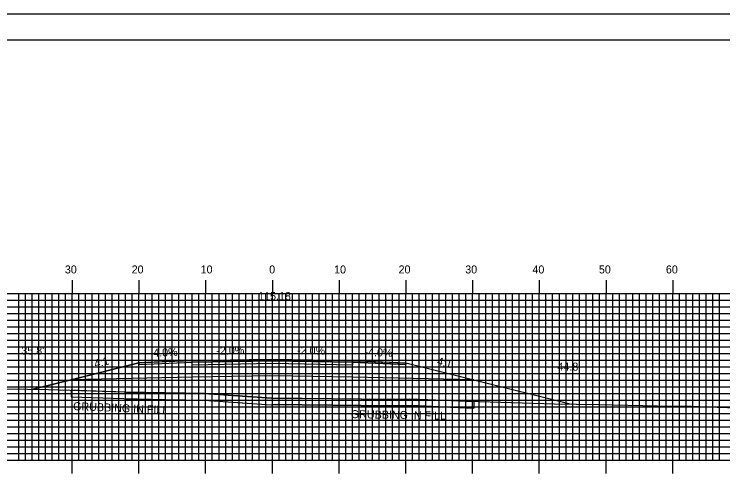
# Model space of a CAD drawing. Extents: x 1772809 to 1773153, y 442591 to 442811.
# Drawn here: x 1772936.4 to 1773042.6, y 442741.2 to 442810.5 of the extents above; entities that cross this region are included whole.
import ezdxf

# ---------------------------------------------------------------- set-up
doc = ezdxf.new("R2010")
doc.units = 0
for name, color, linetype in [('ANNOTATION', 7, 'Continuous'), ('BORDER', 7, 'Continuous'), ('D_Roadway_Centerline', 7, 'Continuous'), ('D_Roadway_Centerline_Text', 7, 'Continuous'), ('D_Roadway_Edge_Shoulder', 7, 'Continuous'), ('D_Roadway_Edge_TW', 7, 'Continuous'), ('D_Roadway_Pavement', 7, 'Continuous'), ('D_Roadway_SlopeLines', 7, 'Continuous'), ('D_Roadway_SubGrade', 7, 'Continuous'), ('D_Text_Standard', 7, 'Continuous'), ('GRUBBING IN FILL', 7, 'Continuous'), ('H_V ANNOTATION', 7, 'Continuous'), ('MAJOR', 7, 'Continuous'), ('MINOR', 7, 'Continuous'), ('PLOT BOUNDARY', 7, 'Continuous'), ('S_Roadway_Centerline', 7, 'Continuous')]:
    doc.layers.add(name, color=color, linetype=linetype)

msp = doc.modelspace()

# ---------------------------------------------------------------- linework, layer by layer
at = {"layer": 'BORDER'}
msp.add_lwpolyline([(1772825.52, 442596.67), (1773145.52, 442596.67), (1773145.52, 442806.67), (1772825.52, 442806.67)], close=True, dxfattribs=at)
at = {"layer": 'D_Roadway_Centerline'}
msp.add_lwpolyline([(1772939.27, 442754.32), (1772943.12, 442755.28), (1772944.95, 442755.74), (1772955.12, 442758.28), (1772957.96, 442758.4), (1772963.12, 442758.6), (1772963.12, 442758.6), (1772971.65, 442758.77), (1772975.12, 442758.84), (1772987.12, 442758.6), (1772987.12, 442758.6), (1772991.4, 442758.43), (1772995.12, 442758.28), (1772999.33, 442757.23), (1773005.29, 442755.74), (1773005.3, 442755.74), (1773019.94, 442752.08)], dxfattribs=at)
at = {"layer": 'D_Roadway_Edge_Shoulder'}
for points in [[(1772963.12, 442758.6), (1772955.12, 442758.28), (1772955.12, 442758.03), (1772963.12, 442758.35)], [(1772987.12, 442758.6), (1772995.12, 442758.28), (1772995.12, 442758.03), (1772987.12, 442758.35)]]:
    msp.add_lwpolyline(points, close=True, dxfattribs=at)
at = {"layer": 'D_Roadway_Edge_TW'}
msp.add_lwpolyline([(1772963.12, 442758.35), (1772963.12, 442758.6), (1772975.12, 442758.84), (1772987.12, 442758.6), (1772987.12, 442758.35), (1772975.12, 442758.59)], close=True, dxfattribs=at)
at = {"layer": 'D_Roadway_Pavement'}
msp.add_lwpolyline([(1772963.12, 442757.94), (1772963.12, 442758.35), (1772975.12, 442758.59), (1772987.12, 442758.35), (1772987.12, 442757.94), (1772975.12, 442758.18)], close=True, dxfattribs=at)
at = {"layer": 'D_Roadway_SlopeLines'}
for points in [[(1772955.12, 442758.28), (1772944.95, 442755.74), (1772943.12, 442755.28), (1772939.27, 442754.32)], [(1772995.12, 442758.28), (1773005.29, 442755.74), (1773019.93, 442752.08)]]:
    msp.add_lwpolyline(points, dxfattribs=at)
at = {"layer": 'D_Roadway_SubGrade'}
msp.add_lwpolyline([(1772963.12, 442756.1), (1772944.95, 442755.74), (1772955.12, 442758.28), (1772955.12, 442758.03), (1772963.12, 442758.35), (1772975.12, 442758.59), (1772987.12, 442758.35), (1772995.12, 442758.03), (1772995.12, 442758.28), (1773005.29, 442755.74), (1772987.12, 442756.1), (1772975.12, 442756.34)], close=True, dxfattribs=at)
at = {"layer": 'GRUBBING IN FILL'}
for p, q in [((1772944.95, 442754.17), (1772944.95, 442753.17)), ((1772944.95, 442754.17), (1772944.95, 442753.17)), ((1773005.29, 442752.48), (1773005.29, 442751.47)), ((1773005.29, 442752.48), (1773005.29, 442751.47))]:
    msp.add_line(p, q, dxfattribs=at)
for points in [[(1772944.95, 442753.17), (1772952.87, 442752.9), (1772958.97, 442752.78), (1772964.88, 442752.66), (1772969.91, 442752.33), (1772974.95, 442751.99), (1772975.12, 442751.99), (1772975.12, 442752.99), (1772974.98, 442752.99), (1772969.95, 442753.33), (1772964.92, 442753.66), (1772959.01, 442753.77), (1772953.09, 442753.89), (1772947.25, 442754.09), (1772944.95, 442754.17)], [(1772944.95, 442753.17), (1772952.87, 442752.9), (1772958.97, 442752.78), (1772964.88, 442752.66), (1772969.91, 442752.33), (1772974.95, 442751.99), (1772975.12, 442751.99), (1772975.12, 442752.99), (1772974.98, 442752.99), (1772969.95, 442753.33), (1772964.92, 442753.66), (1772959.01, 442753.77), (1772953.09, 442753.89), (1772947.25, 442754.09), (1772944.95, 442754.17)], [(1772975.12, 442752.99), (1772978.81, 442752.99), (1772984.02, 442752.91), (1772988.45, 442752.86), (1772992.8, 442752.83), (1772997.16, 442752.81), (1773000.84, 442752.65), (1773005.29, 442752.48), (1773005.29, 442751.47), (1773001.21, 442751.64), (1772997.13, 442751.81), (1772992.79, 442751.83), (1772988.44, 442751.86), (1772984.01, 442751.91), (1772979.57, 442751.97), (1772975.99, 442752), (1772975.12, 442751.99)], [(1772975.12, 442752.99), (1772978.81, 442752.99), (1772984.02, 442752.91), (1772988.45, 442752.86), (1772992.8, 442752.83), (1772997.16, 442752.81), (1773000.84, 442752.65), (1773005.29, 442752.48), (1773005.29, 442751.47), (1773001.21, 442751.64), (1772997.13, 442751.81), (1772992.79, 442751.83), (1772988.44, 442751.86), (1772984.01, 442751.91), (1772979.57, 442751.97), (1772975.99, 442752), (1772975.12, 442751.99)]]:
    msp.add_lwpolyline(points, close=True, dxfattribs=at)
msp.add_lwpolyline([(1772944.95, 442753.17), (1772952.87, 442752.9), (1772953.06, 442752.89), (1772964.88, 442752.66), (1772974.95, 442751.99), (1772977.03, 442752), (1772979.57, 442751.97), (1772988.44, 442751.86), (1772997.13, 442751.81), (1773005.29, 442751.47)], dxfattribs=at)
msp.add_lwpolyline([(1772944.95, 442753.17), (1772952.87, 442752.9), (1772953.06, 442752.89), (1772964.88, 442752.66), (1772974.95, 442751.99), (1772977.03, 442752), (1772979.57, 442751.97), (1772988.44, 442751.86), (1772997.13, 442751.81), (1773005.29, 442751.47)], dxfattribs=at)
at = {"layer": 'MAJOR'}
for p, q in [((1772945.12, 442770.67), (1772945.12, 442768.67)), ((1772955.12, 442770.67), (1772955.12, 442768.67)), ((1772965.12, 442770.67), (1772965.12, 442768.67)), ((1772975.12, 442770.67), (1772975.12, 442768.67)), ((1772985.12, 442770.67), (1772985.12, 442768.67)), ((1772995.12, 442770.67), (1772995.12, 442768.67)), ((1773005.12, 442770.67), (1773005.12, 442768.67)), ((1773015.12, 442770.67), (1773015.12, 442768.67)), ((1773025.12, 442770.67), (1773025.12, 442768.67)), ((1773035.12, 442770.67), (1773035.12, 442768.67)), ((1772835.12, 442768.67), (1773115.12, 442768.67)), ((1772835.12, 442768.67), (1773115.12, 442768.67)), ((1772945.12, 442743.67), (1772945.12, 442768.67)), ((1772955.12, 442743.67), (1772955.12, 442768.67)), ((1772965.12, 442743.67), (1772965.12, 442768.67)), ((1772975.12, 442743.67), (1772975.12, 442768.67)), ((1772985.12, 442743.67), (1772985.12, 442768.67)), ((1772995.12, 442743.67), (1772995.12, 442768.67)), ((1773005.12, 442743.67), (1773005.12, 442768.67)), ((1773015.12, 442743.67), (1773015.12, 442768.67)), ((1773025.12, 442743.67), (1773025.12, 442768.67)), ((1773035.12, 442743.67), (1773035.12, 442768.67)), ((1772835.12, 442763.67), (1773115.12, 442763.67)), ((1772835.12, 442758.67), (1773115.12, 442758.67)), ((1772835.12, 442753.67), (1773115.12, 442753.67)), ((1772835.12, 442748.67), (1773115.12, 442748.67)), ((1772835.12, 442743.67), (1773115.12, 442743.67)), ((1772835.12, 442743.67), (1773115.12, 442743.67)), ((1772945.12, 442741.66), (1772945.12, 442743.67)), ((1772955.12, 442741.66), (1772955.12, 442743.67)), ((1772965.12, 442741.66), (1772965.12, 442743.67)), ((1772975.12, 442741.66), (1772975.12, 442743.67)), ((1772985.12, 442741.66), (1772985.12, 442743.67)), ((1772995.12, 442741.66), (1772995.12, 442743.67)), ((1773005.12, 442741.66), (1773005.12, 442743.67)), ((1773015.12, 442741.66), (1773015.12, 442743.67)), ((1773025.12, 442741.66), (1773025.12, 442743.67)), ((1773035.12, 442741.66), (1773035.12, 442743.67))]:
    msp.add_line(p, q, dxfattribs=at)
at = {"layer": 'MINOR'}
for p, q in [((1772937.12, 442743.67), (1772937.12, 442768.67)), ((1772938.12, 442743.67), (1772938.12, 442768.67)), ((1772939.12, 442743.67), (1772939.12, 442768.67)), ((1772940.12, 442743.67), (1772940.12, 442768.67)), ((1772941.12, 442743.67), (1772941.12, 442768.67)), ((1772942.12, 442743.67), (1772942.12, 442768.67)), ((1772943.12, 442743.67), (1772943.12, 442768.67)), ((1772944.12, 442743.67), (1772944.12, 442768.67)), ((1772946.12, 442743.67), (1772946.12, 442768.67)), ((1772947.12, 442743.67), (1772947.12, 442768.67)), ((1772948.12, 442743.67), (1772948.12, 442768.67)), ((1772949.12, 442743.67), (1772949.12, 442768.67)), ((1772950.12, 442743.67), (1772950.12, 442768.67)), ((1772951.12, 442743.67), (1772951.12, 442768.67)), ((1772952.12, 442743.67), (1772952.12, 442768.67)), ((1772953.12, 442743.67), (1772953.12, 442768.67)), ((1772954.12, 442743.67), (1772954.12, 442768.67)), ((1772956.12, 442743.67), (1772956.12, 442768.67)), ((1772957.12, 442743.67), (1772957.12, 442768.67)), ((1772958.12, 442743.67), (1772958.12, 442768.67)), ((1772959.12, 442743.67), (1772959.12, 442768.67)), ((1772960.12, 442743.67), (1772960.12, 442768.67)), ((1772961.12, 442743.67), (1772961.12, 442768.67)), ((1772962.12, 442743.67), (1772962.12, 442768.67)), ((1772963.12, 442743.67), (1772963.12, 442768.67)), ((1772964.12, 442743.67), (1772964.12, 442768.67)), ((1772966.12, 442743.67), (1772966.12, 442768.67)), ((1772967.12, 442743.67), (1772967.12, 442768.67)), ((1772968.12, 442743.67), (1772968.12, 442768.67)), ((1772969.12, 442743.67), (1772969.12, 442768.67)), ((1772970.12, 442743.67), (1772970.12, 442768.67)), ((1772971.12, 442743.67), (1772971.12, 442768.67)), ((1772972.12, 442743.67), (1772972.12, 442768.67)), ((1772973.12, 442743.67), (1772973.12, 442768.67)), ((1772974.12, 442743.67), (1772974.12, 442768.67)), ((1772976.12, 442743.67), (1772976.12, 442768.67)), ((1772977.12, 442743.67), (1772977.12, 442768.67)), ((1772978.12, 442743.67), (1772978.12, 442768.67)), ((1772979.12, 442743.67), (1772979.12, 442768.67)), ((1772980.12, 442743.67), (1772980.12, 442768.67)), ((1772981.12, 442743.67), (1772981.12, 442768.67)), ((1772982.12, 442743.67), (1772982.12, 442768.67)), ((1772983.12, 442743.67), (1772983.12, 442768.67)), ((1772984.12, 442743.67), (1772984.12, 442768.67)), ((1772986.12, 442743.67), (1772986.12, 442768.67)), ((1772987.12, 442743.67), (1772987.12, 442768.67)), ((1772988.12, 442743.67), (1772988.12, 442768.67)), ((1772989.12, 442743.67), (1772989.12, 442768.67)), ((1772990.12, 442743.67), (1772990.12, 442768.67)), ((1772991.12, 442743.67), (1772991.12, 442768.67)), ((1772992.12, 442743.67), (1772992.12, 442768.67)), ((1772993.12, 442743.67), (1772993.12, 442768.67)), ((1772994.12, 442743.67), (1772994.12, 442768.67)), ((1772996.12, 442743.67), (1772996.12, 442768.67)), ((1772997.12, 442743.67), (1772997.12, 442768.67)), ((1772998.12, 442743.67), (1772998.12, 442768.67)), ((1772999.12, 442743.67), (1772999.12, 442768.67)), ((1773000.12, 442743.67), (1773000.12, 442768.67)), ((1773001.12, 442743.67), (1773001.12, 442768.67)), ((1773002.12, 442743.67), (1773002.12, 442768.67)), ((1773003.12, 442743.67), (1773003.12, 442768.67)), ((1773004.12, 442743.67), (1773004.12, 442768.67)), ((1773006.12, 442743.67), (1773006.12, 442768.67)), ((1773007.12, 442743.67), (1773007.12, 442768.67)), ((1773008.12, 442743.67), (1773008.12, 442768.67)), ((1773009.12, 442743.67), (1773009.12, 442768.67)), ((1773010.12, 442743.67), (1773010.12, 442768.67)), ((1773011.12, 442743.67), (1773011.12, 442768.67)), ((1773012.12, 442743.67), (1773012.12, 442768.67)), ((1773013.12, 442743.67), (1773013.12, 442768.67)), ((1773014.12, 442743.67), (1773014.12, 442768.67)), ((1773016.12, 442743.67), (1773016.12, 442768.67)), ((1773017.12, 442743.67), (1773017.12, 442768.67)), ((1773018.12, 442743.67), (1773018.12, 442768.67)), ((1773019.12, 442743.67), (1773019.12, 442768.67)), ((1773020.12, 442743.67), (1773020.12, 442768.67)), ((1773021.12, 442743.67), (1773021.12, 442768.67)), ((1773022.12, 442743.67), (1773022.12, 442768.67)), ((1773023.12, 442743.67), (1773023.12, 442768.67)), ((1773024.12, 442743.67), (1773024.12, 442768.67)), ((1773026.12, 442743.67), (1773026.12, 442768.67)), ((1773027.12, 442743.67), (1773027.12, 442768.67)), ((1773028.12, 442743.67), (1773028.12, 442768.67)), ((1773029.12, 442743.67), (1773029.12, 442768.67)), ((1773030.12, 442743.67), (1773030.12, 442768.67)), ((1773031.12, 442743.67), (1773031.12, 442768.67)), ((1773032.12, 442743.67), (1773032.12, 442768.67)), ((1773033.12, 442743.67), (1773033.12, 442768.67)), ((1773034.12, 442743.67), (1773034.12, 442768.67)), ((1773036.12, 442743.67), (1773036.12, 442768.67)), ((1773037.12, 442743.67), (1773037.12, 442768.67)), ((1773038.12, 442743.67), (1773038.12, 442768.67)), ((1773039.12, 442743.67), (1773039.12, 442768.67)), ((1773040.12, 442743.67), (1773040.12, 442768.67)), ((1773041.12, 442743.67), (1773041.12, 442768.67)), ((1773042.12, 442743.67), (1773042.12, 442768.67)), ((1772835.12, 442767.67), (1773115.12, 442767.67)), ((1772835.12, 442766.67), (1773115.12, 442766.67)), ((1772835.12, 442765.67), (1773115.12, 442765.67)), ((1772835.12, 442764.67), (1773115.12, 442764.67)), ((1772835.12, 442762.67), (1773115.12, 442762.67)), ((1772835.12, 442761.67), (1773115.12, 442761.67)), ((1772835.12, 442760.67), (1773115.12, 442760.67)), ((1772835.12, 442759.67), (1773115.12, 442759.67)), ((1772835.12, 442757.67), (1773115.12, 442757.67)), ((1772835.12, 442756.67), (1773115.12, 442756.67)), ((1772835.12, 442755.67), (1773115.12, 442755.67)), ((1772835.12, 442754.67), (1773115.12, 442754.67)), ((1772835.12, 442752.67), (1773115.12, 442752.67)), ((1772835.12, 442751.67), (1773115.12, 442751.67)), ((1772835.12, 442750.67), (1773115.12, 442750.67)), ((1772835.12, 442749.67), (1773115.12, 442749.67)), ((1772835.12, 442747.67), (1773115.12, 442747.67)), ((1772835.12, 442746.67), (1773115.12, 442746.67)), ((1772835.12, 442745.67), (1773115.12, 442745.67)), ((1772835.12, 442744.67), (1773115.12, 442744.67))]:
    msp.add_line(p, q, dxfattribs=at)
at = {"layer": 'PLOT BOUNDARY'}
msp.add_lwpolyline([(1772809.33, 442590.55), (1773149.33, 442590.55), (1773149.33, 442810.55), (1772809.33, 442810.55)], close=True, dxfattribs=at)
at = {"layer": 'S_Roadway_Centerline'}
msp.add_lwpolyline([(1772932.13, 442754.44), (1772941.59, 442754.28), (1772952.91, 442753.9), (1772953.09, 442753.89), (1772964.92, 442753.66), (1772974.98, 442752.99), (1772977.04, 442753), (1772979.58, 442752.97), (1772988.45, 442752.86), (1772997.16, 442752.81), (1773004.53, 442752.5), (1773017.39, 442752.11), (1773023.99, 442752.04), (1773035.02, 442751.79), (1773037.94, 442751.76), (1773041.77, 442751.61), (1773055.86, 442751.19)], dxfattribs=at)

# ---------------------------------------------------------------- texts
at = {"layer": 'ANNOTATION'}
for s, rotation, p in [('-2.0%', 1.1457, (1772966.73, 442759.48)), ('-2.0%', 358.8542, (1772978.81, 442759.57)), ('-4.0%', 2.2906, (1772956.75, 442759.15)), ('-4.0%', 357.7093, (1772988.91, 442759.33)), ('4:1', 14.0388, (1772948.57, 442757.51)), ('4:1', 345.9614, (1772999.71, 442758))]:
    msp.add_text(s, height=1.2, rotation=rotation, dxfattribs=at).set_placement(p)
at = {"layer": 'D_Roadway_Centerline'}
for s, p in [('C', (1772975.11, 442758.84)), ('L', (1772975.12, 442758.84))]:
    msp.add_text(s, height=0.0146, dxfattribs=at).set_placement(p)
at = {"layer": 'D_Roadway_Centerline_Text'}
msp.add_text('115.18', height=1.2, dxfattribs=at).set_placement((1772972.99, 442767.68))
at = {"layer": 'D_Text_Standard'}
for s, p in [("35.8'", (1772937.5, 442759.5)), ("44.8'", (1773017.84, 442757.1))]:
    msp.add_text(s, height=1.2, dxfattribs=at).set_placement(p)
at = {"layer": 'GRUBBING IN FILL'}
for rotation, p in [(357.5719, (1772945.24, 442751.19)), (359.0192, (1772986.87, 442749.98))]:
    msp.add_text('GRUBBING IN FILL', height=1.2, rotation=rotation, dxfattribs=at).set_placement(p)
at = {"layer": 'H_V ANNOTATION'}
for s, p in [('30', (1772944.02, 442771.67)), ('20', (1772954.03, 442771.67)), ('10', (1772964.37, 442771.67)), ('0', (1772974.64, 442771.67)), ('10', (1772984.37, 442771.67)), ('20', (1772994.03, 442771.67)), ('30', (1773004.02, 442771.67)), ('40', (1773014.09, 442771.67)), ('50', (1773024.05, 442771.67)), ('60', (1773034.09, 442771.67))]:
    msp.add_text(s, height=1.2, dxfattribs=at).set_placement(p)

doc.saveas('drawing.dxf')
